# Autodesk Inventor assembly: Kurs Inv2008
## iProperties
Shininess: 64.0
Length Units: 11269
Angle Units: 11279
Time Units: 11290
Mass Units: 11283
Length Display Precision: 3
Angle Display Precision: 2
Compacted: True
Part Number: Kurs Inv2008
Document SubType Name: Assembly
Created: 2003-08
Designer: JWe
Manufacturer: Standard
Standards Organization: Custom
Density: 0.0
Volumn: 0.0
Area: 0.0
PropertySet Name: Model Information
Control State: 0
Master: False
Checked Out: False
Author: Administratör
